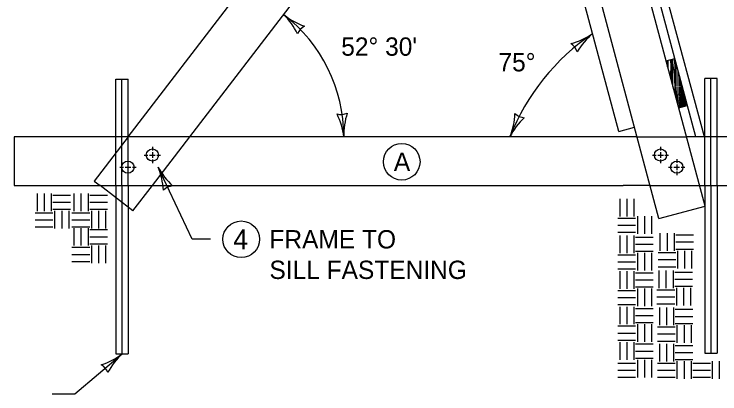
# Model space of a CAD drawing. Extents: x 49991 to 79985, y 47703 to 60542.
# Drawn here: x 50010.675 to 50012.986, y 49992.858 to 49994.102 of the extents above; entities that cross this region are included whole.
import ezdxf

# ---------------------------------------------------------------- set-up
doc = ezdxf.new("R2010")
doc.units = 0
for name, color, linetype in [('Level 1', 7, 'Continuous'), ('Level 2', 7, 'Continuous'), ('Level 3', 7, 'Continuous'), ('Level 4', 7, 'Continuous'), ('Level 5', 7, 'Continuous')]:
    doc.layers.add(name, color=color, linetype=linetype)

msp = doc.modelspace()

# ---------------------------------------------------------------- linework, layer by layer
at = {"layer": 'Level 1'}
for p, q in [((50012.7492, 49993.5717), (50012.0592, 49996.1469)), ((50011.049, 49993.7005), (50012.4061, 49995.4691)), ((50011.2503, 49993.7005), (50012.4582, 49995.2747)), ((50012.655, 49993.7175), (50012.2948, 49995.0618)), ((50012.9351, 49993.7005), (50012.7492, 49994.3944)), ((50012.9075, 49993.7005), (50012.7492, 49994.2915)), ((50012.8544, 49993.782), (50012.7492, 49994.1747)), ((50012.8095, 49993.9495), (50012.8387, 49993.9572)), ((50012.9367, 49993.5408), (50012.9367, 49993.8913)), ((50012.9766, 49993.8913), (50012.9367, 49993.8913)), ((50012.9567, 49993.5408), (50012.9567, 49993.8913)), ((50012.9766, 49993.5408), (50012.9766, 49993.8913)), ((50011.0085, 49993.5408), (50011.0085, 49993.8888)), ((50011.0085, 49993.8888), (50011.0484, 49993.8888)), ((50011.0284, 49993.5408), (50011.0284, 49993.8888)), ((50011.0484, 49993.5408), (50011.0484, 49993.8888)), ((50012.8509, 49993.7952), (50012.88, 49993.803)), ((50012.9373, 49993.4729), (50012.8544, 49993.782)), ((50012.655, 49993.7175), (50012.7064, 49993.7315)), ((50010.6752, 49993.7005), (50010.6752, 49993.5408)), ((50012.7147, 49993.7005), (50010.6752, 49993.7005)), ((50013.2307, 49993.7005), (50012.8762, 49993.7005)), ((50012.7865, 49993.4325), (50012.7492, 49993.5717)), ((50010.6752, 49993.5408), (50012.6693, 49993.5408)), ((50011.0643, 49993.4581), (50010.9566, 49993.5408)), ((50011.0643, 49993.4581), (50011.1278, 49993.5408)), ((50012.7575, 49993.5408), (50012.6693, 49993.5408)), ((50012.9191, 49993.5408), (50013.2307, 49993.5408)), ((50010.7503, 49993.5148), (50010.7503, 49993.457)), ((50010.7735, 49993.5148), (50010.7735, 49993.457)), ((50010.7966, 49993.5148), (50010.7966, 49993.457)), ((50010.802, 49993.5094), (50010.8598, 49993.5094)), ((50010.8709, 49993.5148), (50010.8709, 49993.457)), ((50010.8941, 49993.5148), (50010.8941, 49993.457)), ((50010.9172, 49993.5148), (50010.9172, 49993.457)), ((50010.9226, 49993.5094), (50010.9804, 49993.5094)), ((50012.6583, 49993.4972), (50012.6583, 49993.4394)), ((50012.6815, 49993.4972), (50012.6815, 49993.4394)), ((50012.7046, 49993.4972), (50012.7046, 49993.4394)), ((50010.802, 49993.4863), (50010.8598, 49993.4863)), ((50010.9226, 49993.4863), (50010.9804, 49993.4863)), ((50010.7441, 49993.4516), (50010.802, 49993.4516)), ((50010.802, 49993.4632), (50010.8598, 49993.4632)), ((50010.8077, 49993.4574), (50010.8077, 49993.3996)), ((50010.8309, 49993.4574), (50010.8309, 49993.3996)), ((50010.854, 49993.4574), (50010.854, 49993.3996)), ((50010.8647, 49993.4516), (50010.9226, 49993.4516)), ((50010.9226, 49993.4632), (50010.9804, 49993.4632)), ((50010.9283, 49993.4574), (50010.9283, 49993.3996)), ((50010.9515, 49993.4574), (50010.9515, 49993.3996)), ((50010.9746, 49993.4574), (50010.9746, 49993.3996)), ((50012.7865, 49993.4325), (50012.9373, 49993.4729)), ((50010.7441, 49993.4285), (50010.802, 49993.4285)), ((50010.8647, 49993.4285), (50010.9226, 49993.4285)), ((50012.6521, 49993.434), (50012.71, 49993.434)), ((50012.7157, 49993.4398), (50012.7157, 49993.382)), ((50012.7389, 49993.4398), (50012.7389, 49993.382)), ((50012.762, 49993.4398), (50012.762, 49993.382)), ((50010.7441, 49993.4053), (50010.802, 49993.4053)), ((50010.8647, 49993.4053), (50010.9226, 49993.4053)), ((50012.6521, 49993.4109), (50012.71, 49993.4109)), ((50010.8709, 49993.4015), (50010.8709, 49993.3437)), ((50010.8941, 49993.4015), (50010.8941, 49993.3437)), ((50010.9172, 49993.4015), (50010.9172, 49993.3437)), ((50010.9226, 49993.3961), (50010.9804, 49993.3961)), ((50012.6521, 49993.3877), (50012.71, 49993.3877)), ((50012.7896, 49993.3843), (50012.7896, 49993.3265)), ((50012.8128, 49993.3843), (50012.8128, 49993.3265)), ((50012.8359, 49993.3843), (50012.8359, 49993.3265)), ((50010.9226, 49993.373), (50010.9804, 49993.373)), ((50012.6583, 49993.3771), (50012.6583, 49993.3193)), ((50012.6815, 49993.3771), (50012.6815, 49993.3193)), ((50012.7046, 49993.3771), (50012.7046, 49993.3193)), ((50012.71, 49993.3717), (50012.7678, 49993.3717)), ((50012.8413, 49993.3789), (50012.8991, 49993.3789)), ((50010.8647, 49993.3383), (50010.9226, 49993.3383)), ((50010.9226, 49993.3499), (50010.9804, 49993.3499)), ((50010.9283, 49993.3441), (50010.9283, 49993.2863)), ((50010.9515, 49993.3441), (50010.9515, 49993.2863)), ((50010.9746, 49993.3441), (50010.9746, 49993.2863)), ((50012.71, 49993.3486), (50012.7678, 49993.3486)), ((50012.8413, 49993.3558), (50012.8991, 49993.3558)), ((50010.8647, 49993.3152), (50010.9226, 49993.3152)), ((50012.6521, 49993.3139), (50012.71, 49993.3139)), ((50012.71, 49993.3255), (50012.7678, 49993.3255)), ((50012.7157, 49993.3197), (50012.7157, 49993.2619)), ((50012.7389, 49993.3197), (50012.7389, 49993.2619)), ((50012.762, 49993.3197), (50012.762, 49993.2619)), ((50012.7834, 49993.3211), (50012.8413, 49993.3211)), ((50012.8413, 49993.3327), (50012.8991, 49993.3327)), ((50012.847, 49993.3269), (50012.847, 49993.2691)), ((50012.8702, 49993.3269), (50012.8702, 49993.2691)), ((50012.8933, 49993.3269), (50012.8933, 49993.2691)), ((50010.8647, 49993.292), (50010.9226, 49993.292)), ((50012.6521, 49993.2908), (50012.71, 49993.2908)), ((50012.7834, 49993.298), (50012.8413, 49993.298)), ((50012.6521, 49993.2676), (50012.71, 49993.2676)), ((50012.7834, 49993.2748), (50012.8413, 49993.2748)), ((50012.6583, 49993.2604), (50012.6583, 49993.2026)), ((50012.6815, 49993.2604), (50012.6815, 49993.2026)), ((50012.7046, 49993.2604), (50012.7046, 49993.2026)), ((50012.71, 49993.255), (50012.7678, 49993.255)), ((50012.7862, 49993.2624), (50012.7862, 49993.2046)), ((50012.8094, 49993.2624), (50012.8094, 49993.2046)), ((50012.8325, 49993.2624), (50012.8325, 49993.2046)), ((50012.8379, 49993.257), (50012.8957, 49993.257)), ((50012.71, 49993.2319), (50012.7678, 49993.2319)), ((50012.8379, 49993.2339), (50012.8957, 49993.2339)), ((50012.6521, 49993.1972), (50012.71, 49993.1972)), ((50012.71, 49993.2088), (50012.7678, 49993.2088)), ((50012.7157, 49993.203), (50012.7157, 49993.1452)), ((50012.7389, 49993.203), (50012.7389, 49993.1452)), ((50012.762, 49993.203), (50012.762, 49993.1452)), ((50012.78, 49993.1992), (50012.8379, 49993.1992)), ((50012.8379, 49993.2108), (50012.8957, 49993.2108)), ((50012.8436, 49993.205), (50012.8436, 49993.1472)), ((50012.8668, 49993.205), (50012.8668, 49993.1472)), ((50012.8899, 49993.205), (50012.8899, 49993.1472)), ((50012.6521, 49993.1741), (50012.71, 49993.1741)), ((50012.78, 49993.1761), (50012.8379, 49993.1761)), ((50012.6521, 49993.1509), (50012.71, 49993.1509)), ((50012.78, 49993.1529), (50012.8379, 49993.1529)), ((50012.6583, 49993.1437), (50012.6583, 49993.0859)), ((50012.6815, 49993.1437), (50012.6815, 49993.0859)), ((50012.7046, 49993.1437), (50012.7046, 49993.0859)), ((50012.71, 49993.1383), (50012.7678, 49993.1383)), ((50012.7879, 49993.1406), (50012.7879, 49993.0828)), ((50012.8111, 49993.1406), (50012.8111, 49993.0828)), ((50012.8342, 49993.1406), (50012.8342, 49993.0828)), ((50012.8396, 49993.1352), (50012.8974, 49993.1352)), ((50012.71, 49993.1152), (50012.7678, 49993.1152)), ((50012.8396, 49993.1121), (50012.8974, 49993.1121)), ((50012.71, 49993.0921), (50012.7678, 49993.0921)), ((50012.7157, 49993.0863), (50012.7157, 49993.0285)), ((50012.7389, 49993.0863), (50012.7389, 49993.0285)), ((50012.762, 49993.0863), (50012.762, 49993.0285)), ((50012.8396, 49993.089), (50012.8974, 49993.089)), ((50012.8453, 49993.0832), (50012.8453, 49993.0254)), ((50012.8685, 49993.0832), (50012.8685, 49993.0254)), ((50012.8916, 49993.0832), (50012.8916, 49993.0254)), ((50012.6521, 49993.0805), (50012.71, 49993.0805)), ((50012.7817, 49993.0774), (50012.8396, 49993.0774)), ((50012.6521, 49993.0574), (50012.71, 49993.0574)), ((50012.7817, 49993.0543), (50012.8396, 49993.0543)), ((50012.6521, 49993.0342), (50012.71, 49993.0342)), ((50012.6583, 49993.027), (50012.6583, 49992.9692)), ((50012.6815, 49993.027), (50012.6815, 49992.9692)), ((50012.7046, 49993.027), (50012.7046, 49992.9692)), ((50012.71, 49993.0216), (50012.7678, 49993.0216)), ((50012.7817, 49993.0311), (50012.8396, 49993.0311)), ((50012.7879, 49993.0222), (50012.7879, 49992.9644)), ((50012.8111, 49993.0222), (50012.8111, 49992.9644)), ((50012.8342, 49993.0222), (50012.8342, 49992.9644)), ((50012.8396, 49993.0168), (50012.8974, 49993.0168)), ((50012.71, 49992.9985), (50012.7678, 49992.9985)), ((50012.8396, 49992.9937), (50012.8974, 49992.9937)), ((50012.71, 49992.9754), (50012.7678, 49992.9754)), ((50012.7157, 49992.9696), (50012.7157, 49992.9118)), ((50012.7389, 49992.9696), (50012.7389, 49992.9118)), ((50012.762, 49992.9696), (50012.762, 49992.9118)), ((50012.8396, 49992.9706), (50012.8974, 49992.9706)), ((50012.6521, 49992.959), (50012.71, 49992.959)), ((50012.7817, 49992.959), (50012.8396, 49992.959)), ((50012.8453, 49992.9648), (50012.8453, 49992.907)), ((50012.8685, 49992.9648), (50012.8685, 49992.907)), ((50012.8916, 49992.9648), (50012.8916, 49992.907)), ((50012.8971, 49992.959), (50012.955, 49992.959)), ((50012.9607, 49992.9648), (50012.9607, 49992.907)), ((50012.9839, 49992.9648), (50012.9839, 49992.907)), ((50012.6521, 49992.9359), (50012.71, 49992.9359)), ((50012.7817, 49992.9359), (50012.8396, 49992.9359)), ((50012.8971, 49992.9359), (50012.955, 49992.9359)), ((50012.6521, 49992.9128), (50012.71, 49992.9128)), ((50012.7817, 49992.9127), (50012.8396, 49992.9127)), ((50012.8971, 49992.9127), (50012.955, 49992.9127))]:
    msp.add_line(p, q, dxfattribs=at)
for points in [[(50012.8149, 49993.9294), (50012.8135, 49993.9505)], [(50012.8167, 49993.9227), (50012.8165, 49993.9504), (50012.8165, 49993.9513)], [(50012.8273, 49993.8832), (50012.8253, 49993.905), (50012.8266, 49993.9294), (50012.8253, 49993.9534), (50012.8253, 49993.9537)], [(50012.8298, 49993.8739), (50012.8293, 49993.893), (50012.8291, 49993.9121), (50012.8307, 49993.9256), (50012.8295, 49993.9402), (50012.8302, 49993.9539), (50012.8302, 49993.955)], [(50012.8321, 49993.8652), (50012.8318, 49993.9028), (50012.8323, 49993.9073), (50012.8334, 49993.9096), (50012.8339, 49993.9258), (50012.8323, 49993.9439), (50012.8328, 49993.9557)], [(50012.839, 49993.8394), (50012.8384, 49993.9116), (50012.8391, 49993.9324), (50012.8379, 49993.9439), (50012.8381, 49993.9502), (50012.8389, 49993.956)], [(50012.8432, 49993.8662), (50012.8425, 49993.9036), (50012.8427, 49993.9336), (50012.8432, 49993.9399)], [(50012.8483, 49993.921), (50012.8483, 49993.9211)], [(50012.8498, 49993.8662), (50012.8495, 49993.9036), (50012.8491, 49993.9138), (50012.8483, 49993.921)], [(50012.8254, 49993.9039), (50012.8254, 49993.9039)], [(50012.8543, 49993.8662), (50012.8547, 49993.8958), (50012.8548, 49993.8968)], [(50012.8588, 49993.8662), (50012.8586, 49993.8824)], [(50012.8604, 49993.7977), (50012.8602, 49993.8062), (50012.8604, 49993.8232), (50012.8616, 49993.8455), (50012.8604, 49993.8766)], [(50012.8638, 49993.7986), (50012.8645, 49993.8175), (50012.8645, 49993.8403), (50012.8638, 49993.852), (50012.8629, 49993.8671)], [(50012.8427, 49993.8261), (50012.8436, 49993.84), (50012.8432, 49993.8635)], [(50012.8517, 49993.7954), (50012.8472, 49993.8235), (50012.8475, 49993.833), (50012.8488, 49993.8408), (50012.8495, 49993.8513), (50012.8498, 49993.8635)], [(50012.8548, 49993.7962), (50012.855, 49993.8054), (50012.8538, 49993.8131), (50012.8525, 49993.8182), (50012.8525, 49993.8292), (50012.8549, 49993.8455), (50012.8543, 49993.8635)], [(50012.8583, 49993.7972), (50012.8581, 49993.8062), (50012.8569, 49993.8255), (50012.8594, 49993.8455), (50012.8588, 49993.8635)], [(50012.8682, 49993.7998), (50012.8684, 49993.8207), (50012.8679, 49993.8479)], [(50012.8434, 49993.8368), (50012.8434, 49993.8369)], [(50012.8712, 49993.8006), (50012.8715, 49993.8345)], [(50012.8741, 49993.8014), (50012.874, 49993.8044), (50012.8745, 49993.8233)]]:
    msp.add_lwpolyline(points, dxfattribs=at)
for centre in [(50011.1278, 49993.6406), (50012.7915, 49993.6406), (50011.0479, 49993.6007), (50012.8447, 49993.6007)]:
    msp.add_circle(centre, 0.02, dxfattribs=at)
at = {"layer": 'Level 2'}
for centre in [(50011.9442, 49993.6186), (50011.4187, 49993.3645)]:
    msp.add_circle(centre, 0.06, dxfattribs=at)
at = {"layer": 'Level 3'}
for p, q in [((50011.2586, 49993.3645), (50011.1464, 49993.6012)), ((50011.3187, 49993.3645), (50011.2586, 49993.3645)), ((50010.8736, 49992.858), (50011.0295, 49992.9896)), ((50010.7998, 49992.858), (50010.8736, 49992.858))]:
    msp.add_line(p, q, dxfattribs=at)
for centre, radius, start, end in [((50011.2503, 49993.7005), 0.5046, 0, 52.5006), ((50011.4026, 49993.9413), 0.2223, 25.6593, 45.8428), ((50011.704, 49994.282), 0.233, 231.0306, 250.2805), ((50011.6531, 49994.0154), 0.0548, 120.3421, 156.0645), ((50012.9787, 49993.433), 0.7307, 124.0923, 158.5288), ((50012.4428, 49994.2211), 0.2223, 284.4429, 304.6264), ((50012.7183, 49993.8592), 0.233, 129.8142, 149.0641), ((50012.4667, 49993.961), 0.0548, 19.1257, 54.8481), ((50011.7453, 49993.8284), 0.0548, 256.4357, 292.1581), ((50011.5237, 49993.6716), 0.233, 7.1242, 26.3741), ((50011.9771, 49993.708), 0.2223, 161.7529, 181.9364), ((50012.0822, 49993.7866), 0.233, 338.3039, 357.5537), ((50012.3519, 49993.8171), 0.0548, 227.6154, 263.3377), ((50012.497, 49993.6), 0.2223, 132.9326, 153.1161), ((50010.9418, 49993.5144), 0.2223, 2.8037, 22.9872), ((50011.3518, 49993.7113), 0.233, 208.175, 227.4249), ((50011.2013, 49993.4854), 0.0548, 97.4865, 133.2089), ((50010.8932, 49993.1652), 0.2223, 287.6349, 307.8184), ((50011.1884, 49992.8192), 0.233, 133.0062, 152.256), ((50010.9316, 49992.9069), 0.0548, 22.3177, 58.04)]:
    msp.add_arc(centre, radius, start, end, dxfattribs=at)
at = {"layer": 'Level 4'}
for p, q in [((50012.6693, 49993.8699), (50012.6693, 49993.8699)), ((50012.6693, 49993.7214), (50012.6693, 49993.7214)), ((50011.049, 49993.7005), (50010.9376, 49993.5553)), ((50011.1278, 49993.5408), (50011.2503, 49993.7005)), ((50012.7147, 49993.7005), (50012.8762, 49993.7005)), ((50010.9376, 49993.5553), (50010.9566, 49993.5408)), ((50011.0085, 49993.5408), (50011.0085, 49992.9896)), ((50011.0284, 49993.5408), (50011.0284, 49992.9896)), ((50011.0484, 49993.5408), (50011.0484, 49992.9896)), ((50012.7492, 49993.5408), (50012.7492, 49993.5408)), ((50012.7575, 49993.5408), (50012.9191, 49993.5408)), ((50012.9367, 49993.5408), (50012.9367, 49993.475)), ((50012.9567, 49993.5408), (50012.9567, 49992.9917)), ((50012.9766, 49993.5408), (50012.9766, 49992.9917)), ((50012.9367, 49993.4728), (50012.9367, 49992.9917)), ((50011.0085, 49992.9896), (50011.0484, 49992.9896)), ((50012.9367, 49992.9917), (50012.9766, 49992.9917))]:
    msp.add_line(p, q, dxfattribs=at)
at = {"layer": 'Level 5'}
for p, q in [((50011.1278, 49993.6672), (50011.1278, 49993.6551)), ((50012.7915, 49993.6672), (50012.7915, 49993.6551)), ((50011.1011, 49993.6406), (50011.1132, 49993.6406)), ((50011.1185, 49993.6406), (50011.137, 49993.6406)), ((50011.1278, 49993.6499), (50011.1278, 49993.6313)), ((50011.1423, 49993.6406), (50011.1544, 49993.6406)), ((50012.7649, 49993.6406), (50012.777, 49993.6406)), ((50012.7822, 49993.6406), (50012.8008, 49993.6406)), ((50012.7915, 49993.6499), (50012.7915, 49993.6313)), ((50012.806, 49993.6406), (50012.8181, 49993.6406)), ((50011.0479, 49993.6273), (50011.0479, 49993.6152)), ((50011.1278, 49993.6261), (50011.1278, 49993.614)), ((50012.7915, 49993.6261), (50012.7915, 49993.614)), ((50012.8447, 49993.6273), (50012.8447, 49993.6152)), ((50011.0213, 49993.6007), (50011.0334, 49993.6007)), ((50011.0386, 49993.6007), (50011.0572, 49993.6007)), ((50011.0479, 49993.6099), (50011.0479, 49993.5914)), ((50011.0624, 49993.6007), (50011.0745, 49993.6007)), ((50012.8181, 49993.6007), (50012.8302, 49993.6007)), ((50012.8355, 49993.6007), (50012.854, 49993.6007)), ((50012.8447, 49993.6099), (50012.8447, 49993.5914)), ((50012.8593, 49993.6007), (50012.8714, 49993.6007)), ((50011.0479, 49993.5862), (50011.0479, 49993.5741)), ((50012.8447, 49993.5862), (50012.8447, 49993.5741))]:
    msp.add_line(p, q, dxfattribs=at)

# ---------------------------------------------------------------- texts
at = {"layer": 'Level 2'}
for s, height, p in [("52° 30'", 0.06, (50011.7462, 49993.9659)), ('75°', 0.06, (50012.2609, 49993.9146)), ('A', 0.06, (50011.9184, 49993.5886)), ('4', 0.065, (50011.3927, 49993.332)), ('FRAME TO ', 0.06, (50011.5111, 49993.3345)), ('SILL FASTENING', 0.06, (50011.5111, 49993.2345))]:
    msp.add_text(s, height=height, dxfattribs=at).set_placement(p)

doc.saveas('drawing.dxf')
